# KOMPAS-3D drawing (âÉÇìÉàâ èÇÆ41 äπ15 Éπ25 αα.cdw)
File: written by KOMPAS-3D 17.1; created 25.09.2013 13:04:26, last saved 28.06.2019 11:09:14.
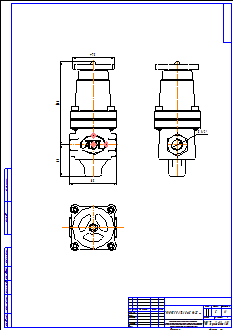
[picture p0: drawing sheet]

Sheet 1: A2, portrait

Title block, sheet 1: name: ГРАНРЕГ КАТ41 Ду15 Ру25 рр; material: Внимание! Данный продукт является объектом авторского права ООО «Торговый Дом АДЛ». / Запрещается изменение, копирование, распространение / (в том числе путем копирования на другие сайты и ресурсы в Интернете) / или любое иное использование информации и объектов без предварительного / согласия правообладателя (ООО «Торговый Дом АДЛ»).; mass: 5; sheets: 1; organisation: ООО "Торговый дом АДЛ"; sheet format: A2; stored path: \\adlc.lan\data\АДЛ_ПКД\3D-модели\ADL production\Клапаны КАТ ГРАНРЕГ\КАТ41\KOMPAS 2D\ГРАНРЕГ КАТ41 Ду15 Ру25 рр.cdw

Views: Вид 1, Проекционный вид 2, Проекционный вид 3
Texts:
  Klimkovich
  ADL
Dimensions and other numbers on the sheet: 75; 85; 57; 150; 1:1; 1; 5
